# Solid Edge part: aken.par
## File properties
Author: Administrator
Template: Normal.par
Last saved by: Administrator
Revision: 3
Application: Solid Edge
Accuracy: 0,990
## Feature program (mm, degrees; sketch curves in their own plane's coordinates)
sketch for "unnamed Protrusion 1" plane through (0, 0, 0) normal (0, -1, 0) x-axis (1, 0, 0)
  arc centre (-46.8726, 15.5213) radius 7.5 from (-54.3726, 15.5213) to (-46.8726, 23.0213) cw
  line (-46.8726, 23.0213) -> (63.1274, 23.0213)
  arc centre (63.1274, 15.5213) radius 7.5 from (63.1274, 23.0213) to (70.6274, 15.5213) cw
  line (70.6274, 15.5213) -> (70.6274, 10.5213)
  arc centre (63.1274, 10.5213) radius 7.5 from (63.1274, 3.0213) to (70.6274, 10.5213) ccw
  line (-46.8726, 3.0213) -> (63.1274, 3.0213)
  arc centre (-46.8726, 10.5213) radius 7.5 from (-54.3726, 10.5213) to (-46.8726, 3.0213) ccw
  line (-54.3726, 15.5213) -> (-54.3726, 10.5213)
extrude "unnamed Protrusion 1" add finite 2.5 along -normal
sketch for "ExtrudedProtrusion_4" #1 plane through (0, 0, 0) normal (0, -1, 0) x-axis (1, 0, 0)
  arc centre (-46.8726, 15.5213) radius 8.5 from (-55.3726, 15.5213) to (-46.8726, 24.0213) cw
  line (-46.8726, 24.0213) -> (63.1274, 24.0213)
  arc centre (63.1274, 15.5213) radius 8.5 from (63.1274, 24.0213) to (71.6274, 15.5213) cw
  line (71.6274, 15.5213) -> (71.6274, 10.5213)
  arc centre (63.1274, 10.5213) radius 8.5 from (71.6274, 10.5213) to (63.1274, 2.0213) cw
  line (63.1274, 2.0213) -> (-46.8726, 2.0213)
  arc centre (-46.8726, 10.5213) radius 8.5 from (-46.8726, 2.0213) to (-55.3726, 10.5213) cw
  line (-55.3726, 10.5213) -> (-55.3726, 15.5213)
sketch for "ExtrudedProtrusion_4" #2 plane through (0, 0, 0) normal (0, -1, 0) x-axis (1, 0, 0)
  arc centre (-46.8726, 15.5213) radius 6.5 from (-53.3726, 15.5213) to (-46.8726, 22.0213) cw
  line (-46.8726, 22.0213) -> (63.1274, 22.0213)
  arc centre (63.1274, 15.5213) radius 6.5 from (63.1274, 22.0213) to (69.6274, 15.5213) cw
  line (69.6274, 15.5213) -> (69.6274, 10.5213)
  arc centre (63.1274, 10.5213) radius 6.5 from (69.6274, 10.5213) to (63.1274, 4.0213) cw
  line (63.1274, 4.0213) -> (-46.8726, 4.0213)
  arc centre (-46.8726, 10.5213) radius 6.5 from (-46.8726, 4.0213) to (-53.3726, 10.5213) cw
  line (-53.3726, 10.5213) -> (-53.3726, 15.5213)
extrude "ExtrudedProtrusion_4" add finite 1 along +normal
fillet "Round_3" radius 1
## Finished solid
Body 1: solid body, 19 faces, 48 edges, 32 vertices.
  Faces by surface: cylinder 8, plane 7, torus 4
  Edges by curve: circle 24, line 24
Bounding box of the edges (mm; curved faces can reach further): 127.000 x 3.500 x 22.000, from (-55.3726, -1, 2.0213) to (71.6274, 2.5, 24.0213).
Cylindrical faces by radius (mm): R1 x4, R7.5 x4
Toroidal faces (ring radius, tube radius in mm): R7.5 r1 x4
Planar faces by outward normal: +x 1, +y 2, +z 1, -x 1, -y 1, -z 1
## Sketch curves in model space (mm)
arc centre (63.1274, 0, 15.5213) radius 7.5 from (63.1274, 0, 23.0213) through (68.5827, 0, 20.6681) to (70.6274, 0, 15.5213)
line (70.6274, 0, 15.5213) -> (70.6274, 0, 10.5213)
arc centre (63.1274, 0, 10.5213) radius 7.5 from (63.1274, 0, 3.0213) through (68.5827, 0, 5.3745) to (70.6274, 0, 10.5213)
line (-46.8726, 0, 3.0213) -> (63.1274, 0, 3.0213)
arc centre (-46.8726, 0, 10.5213) radius 7.5 from (-54.3726, 0, 10.5213) through (-52.0194, 0, 5.066) to (-46.8726, 0, 3.0213)
line (-54.3726, 0, 15.5213) -> (-54.3726, 0, 10.5213)
arc centre (-46.8726, 0, 15.5213) radius 7.5 from (-54.3726, 0, 15.5213) through (-52.0194, 0, 20.9766) to (-46.8726, 0, 23.0213)
line (-46.8726, 0, 23.0213) -> (63.1274, 0, 23.0213)
arc centre (63.1274, 0, 15.5213) radius 8.5 from (63.1274, 0, 24.0213) through (69.3101, 0, 21.3544) to (71.6274, 0, 15.5213)
line (71.6274, 0, 15.5213) -> (71.6274, 0, 10.5213)
arc centre (63.1274, 0, 10.5213) radius 8.5 from (71.6274, 0, 10.5213) through (68.9605, 0, 4.3387) to (63.1274, 0, 2.0213)
line (63.1274, 0, 2.0213) -> (-46.8726, 0, 2.0213)
arc centre (-46.8726, 0, 10.5213) radius 8.5 from (-46.8726, 0, 2.0213) through (-53.0552, 0, 4.6883) to (-55.3726, 0, 10.5213)
line (-55.3726, 0, 10.5213) -> (-55.3726, 0, 15.5213)
arc centre (-46.8726, 0, 15.5213) radius 8.5 from (-55.3726, 0, 15.5213) through (-52.7056, 0, 21.704) to (-46.8726, 0, 24.0213)
line (-46.8726, 0, 24.0213) -> (63.1274, 0, 24.0213)
arc centre (63.1274, 0, 15.5213) radius 6.5 from (63.1274, 0, 22.0213) through (67.8554, 0, 19.9819) to (69.6274, 0, 15.5213)
line (69.6274, 0, 15.5213) -> (69.6274, 0, 10.5213)
arc centre (63.1274, 0, 10.5213) radius 6.5 from (69.6274, 0, 10.5213) through (67.588, 0, 5.7934) to (63.1274, 0, 4.0213)
line (63.1274, 0, 4.0213) -> (-46.8726, 0, 4.0213)
arc centre (-46.8726, 0, 10.5213) radius 6.5 from (-46.8726, 0, 4.0213) through (-51.6005, 0, 6.0608) to (-53.3726, 0, 10.5213)
line (-53.3726, 0, 10.5213) -> (-53.3726, 0, 15.5213)
arc centre (-46.8726, 0, 15.5213) radius 6.5 from (-53.3726, 0, 15.5213) through (-51.3331, 0, 20.2493) to (-46.8726, 0, 22.0213)
line (-46.8726, 0, 22.0213) -> (63.1274, 0, 22.0213)
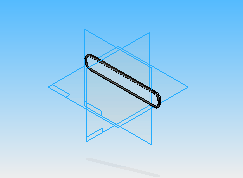
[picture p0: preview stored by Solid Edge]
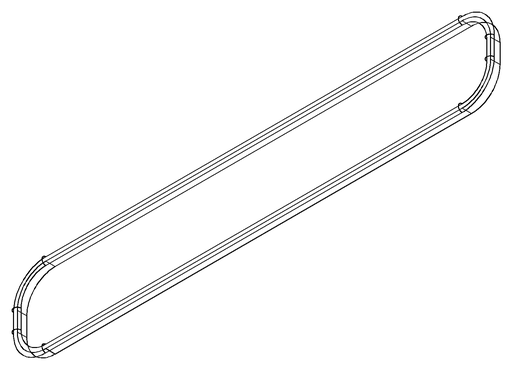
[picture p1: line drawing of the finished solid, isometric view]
